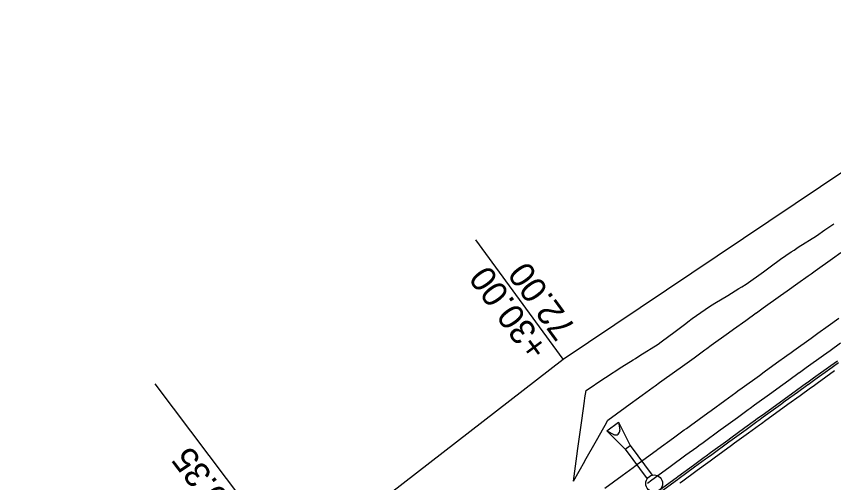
# Model space of a CAD drawing. Extents: x 1147550 to 1149124, y 2017436 to 2018779.
# Drawn here: x 1147906 to 1148099.8, y 2017904.1 to 2018014.6 of the extents above; entities that cross this region are included whole.
import ezdxf

# ---------------------------------------------------------------- set-up
doc = ezdxf.new("R2010")
doc.units = 0
for name, color, linetype in [('S_EDGE_CONCRETE', 7, 'Continuous'), ('S_ELECTRIC_UTILITIES', 7, 'Continuous'), ('S_MAILBOX', 7, 'Continuous'), ('S_RDW_PT_SYM', 7, 'Continuous'), ('S_SECONDARY_CTL', 7, 'Continuous'), ('S_TELEPHONE_UTILITIES', 7, 'Continuous'), ('S_TELEPHONE_UTILITIES_ANNOT', 7, 'Continuous'), ('S_UTL_PT_SYM', 7, 'Continuous')]:
    doc.layers.add(name, color=color, linetype=linetype)

msp = doc.modelspace()

# ---------------------------------------------------------------- linework, layer by layer
at = {"layer": 'S_EDGE_CONCRETE'}
msp.add_arc((1151464.82, 2013253.76), 5729.58, 124.62946, 129.43332, dxfattribs=at)
at = {"layer": 'S_ELECTRIC_UTILITIES'}
msp.add_lwpolyline([(1148035.64, 2017933.4), (1148014.95, 2017961.63)], dxfattribs=at)
at = {"layer": 'S_MAILBOX'}
msp.add_lwpolyline([(1147550.1, 2017525.89), (1147894.72, 2017801.4), (1147903.55, 2017831.14), (1148035.64, 2017933.4), (1148261.5, 2018084.85), (1148285.74, 2018084.65), (1148479.1, 2018223.18), (1148835.76, 2018573.62)], dxfattribs=at)
at = {"layer": 'S_RDW_PT_SYM'}
msp.add_lwpolyline([(1148011.14, 2017831.73), (1147938.86, 2017927.53)], dxfattribs=at)
at = {"layer": 'S_SECONDARY_CTL'}
msp.add_lwpolyline([(1148038.06, 2017904.51), (1148039.06, 2017911.56), (1148039.07, 2017911.65), (1148040.04, 2017918.85), (1148040.66, 2017923.46), (1148040.78, 2017924.26), (1148041.07, 2017925.99), (1148045.28, 2017928.79), (1148045.65, 2017929.04), (1148049.53, 2017931.54), (1148052.25, 2017933.23), (1148052.78, 2017933.56), (1148053.84, 2017934.22), (1148058.13, 2017936.91), (1148058.88, 2017937.48), (1148062.17, 2017939.95), (1148064.71, 2017941.86), (1148065.19, 2017942.22), (1148066.21, 2017942.99), (1148070.35, 2017945.88), (1148071.59, 2017946.63), (1148074.68, 2017948.51), (1148077.28, 2017950.09), (1148077.33, 2017950.12), (1148077.98, 2017950.51), (1148079.01, 2017951.16), (1148083.12, 2017954.09), (1148084.69, 2017955.24), (1148087.2, 2017957.08), (1148089.69, 2017958.82), (1148090.38, 2017959.25), (1148091.4, 2017959.89), (1148095.69, 2017962.58), (1148097.69, 2017964), (1148099.83, 2017965.48)], dxfattribs=at)
at = {"layer": 'S_TELEPHONE_UTILITIES'}
for points in [[(1148045.55, 2017902.83), (1148049.61, 2017905.82), (1148052.2, 2017907.72), (1148052.66, 2017908.06), (1148053.67, 2017908.79), (1148057.73, 2017911.77), (1148058.09, 2017912.03), (1148061.8, 2017914.74), (1148064.36, 2017916.61), (1148064.87, 2017916.98), (1148065.87, 2017917.71), (1148069.94, 2017920.67), (1148070.7, 2017921.23), (1148074.01, 2017923.63), (1148076.58, 2017925.5), (1148077.06, 2017925.85), (1148078.09, 2017926.59), (1148082.17, 2017929.55), (1148083.34, 2017930.39), (1148086.25, 2017932.5), (1148088.7, 2017934.26), (1148088.75, 2017934.3), (1148089.36, 2017934.74), (1148090.34, 2017935.44), (1148094.42, 2017938.38), (1148096, 2017939.52), (1148098.51, 2017941.32), (1148100.97, 2017943.09)], [(1148055.62, 2017904.02), (1148056.63, 2017904.76), (1148060.69, 2017907.73), (1148061.04, 2017907.99), (1148064.75, 2017910.7), (1148067.31, 2017912.57), (1148067.81, 2017912.94), (1148068.81, 2017913.67), (1148072.88, 2017916.63), (1148073.64, 2017917.18), (1148076.95, 2017919.59), (1148079.52, 2017921.45), (1148080, 2017921.8), (1148081.02, 2017922.54), (1148085.1, 2017925.49), (1148086.27, 2017926.34), (1148089.18, 2017928.44), (1148091.63, 2017930.21), (1148091.67, 2017930.24), (1148092.28, 2017930.68), (1148093.26, 2017931.39), (1148097.34, 2017934.33), (1148098.92, 2017935.46), (1148101.43, 2017937.26)], [(1148058.4, 2017902.34), (1148062.46, 2017905.31), (1148062.81, 2017905.57), (1148066.52, 2017908.28), (1148069.08, 2017910.15), (1148069.58, 2017910.52), (1148070.58, 2017911.24), (1148074.65, 2017914.2), (1148075.41, 2017914.76), (1148078.71, 2017917.16), (1148081.28, 2017919.02), (1148081.76, 2017919.37), (1148082.79, 2017920.11), (1148086.86, 2017923.06), (1148088.03, 2017923.91), (1148090.93, 2017926.01), (1148093.38, 2017927.78), (1148093.43, 2017927.81), (1148094.04, 2017928.25), (1148095.01, 2017928.95), (1148099.09, 2017931.89), (1148100.67, 2017933.02)], [(1148058.69, 2017901.94), (1148062.75, 2017904.91), (1148063.11, 2017905.17), (1148066.81, 2017907.88), (1148069.37, 2017909.74), (1148069.88, 2017910.11), (1148070.87, 2017910.84), (1148074.94, 2017913.8), (1148075.7, 2017914.35), (1148079.01, 2017916.76), (1148081.57, 2017918.62), (1148082.05, 2017918.97), (1148083.08, 2017919.71), (1148087.15, 2017922.66), (1148088.32, 2017923.5), (1148091.23, 2017925.6), (1148093.67, 2017927.37), (1148093.72, 2017927.4), (1148094.33, 2017927.84), (1148095.31, 2017928.55), (1148099.39, 2017931.49), (1148100.96, 2017932.62)], [(1148063.34, 2017904.1), (1148063.7, 2017904.36), (1148067.4, 2017907.07), (1148069.96, 2017908.94), (1148070.46, 2017909.3), (1148071.46, 2017910.03), (1148075.53, 2017912.99), (1148076.29, 2017913.54), (1148079.6, 2017915.95), (1148082.16, 2017917.81), (1148082.64, 2017918.16), (1148083.67, 2017918.9), (1148087.74, 2017921.85), (1148088.9, 2017922.69), (1148091.81, 2017924.79), (1148094.26, 2017926.56), (1148094.3, 2017926.59), (1148094.91, 2017927.03), (1148095.89, 2017927.74), (1148099.97, 2017930.67)]]:
    msp.add_lwpolyline(points, dxfattribs=at)
at = {"layer": 'S_TELEPHONE_UTILITIES_ANNOT'}
for p, q in [((1148045.96, 2017916.43), (1148048.72, 2017918.45)), ((1148048.72, 2017918.45), (1148051.54, 2017912.97)), ((1148048.72, 2017918.45), (1148049.06, 2017916.6)), ((1148045.96, 2017916.43), (1148050.33, 2017912.09)), ((1148045.96, 2017916.43), (1148047.64, 2017915.53)), ((1148050.33, 2017912.09), (1148051.54, 2017912.97)), ((1148050.33, 2017912.09), (1148055.52, 2017905.01)), ((1148051.54, 2017912.97), (1148056.73, 2017905.89))]:
    msp.add_line(p, q, dxfattribs=at)
msp.add_circle((1148057.22, 2017903.95), 2, dxfattribs=at)
msp.add_arc((1148048.08, 2017916.43), 1, 239.859, 11.5093, dxfattribs=at)
at = {"layer": 'S_UTL_PT_SYM'}
msp.add_lwpolyline([(1148038.06, 2017904.51), (1148040.75, 2017909.26), (1148040.78, 2017909.32), (1148043.51, 2017914.13), (1148045.25, 2017917.2), (1148045.56, 2017917.74), (1148046.24, 2017918.94), (1148050.32, 2017921.9), (1148050.68, 2017922.16), (1148054.41, 2017924.86), (1148056.98, 2017926.73), (1148057.49, 2017927.1), (1148058.5, 2017927.83), (1148062.58, 2017930.79), (1148063.35, 2017931.34), (1148066.68, 2017933.74), (1148069.25, 2017935.6), (1148069.74, 2017935.95), (1148070.77, 2017936.69), (1148074.87, 2017939.64), (1148076.04, 2017940.48), (1148078.97, 2017942.58), (1148081.43, 2017944.35), (1148081.47, 2017944.38), (1148082.09, 2017944.82), (1148083.07, 2017945.52), (1148087.17, 2017948.46), (1148088.76, 2017949.59), (1148091.28, 2017951.4), (1148093.75, 2017953.16), (1148094.41, 2017953.63), (1148095.39, 2017954.33), (1148099.5, 2017957.25), (1148101.5, 2017958.67)], dxfattribs=at)

# ---------------------------------------------------------------- texts
at = {"layer": 'S_ELECTRIC_UTILITIES'}
for s, p in [('+30.00', (1148032.47, 2017936.03)), ('72.00', (1148038.92, 2017940.76))]:
    msp.add_text(s, height=6, rotation=126.2335, dxfattribs=at).set_placement(p)
at = {"layer": 'S_RDW_PT_SYM'}
msp.add_text('P.I. 46+50.35', height=6, rotation=127.0314, dxfattribs=at).set_placement((1147976.1, 2017874.85))

doc.saveas('drawing.dxf')
